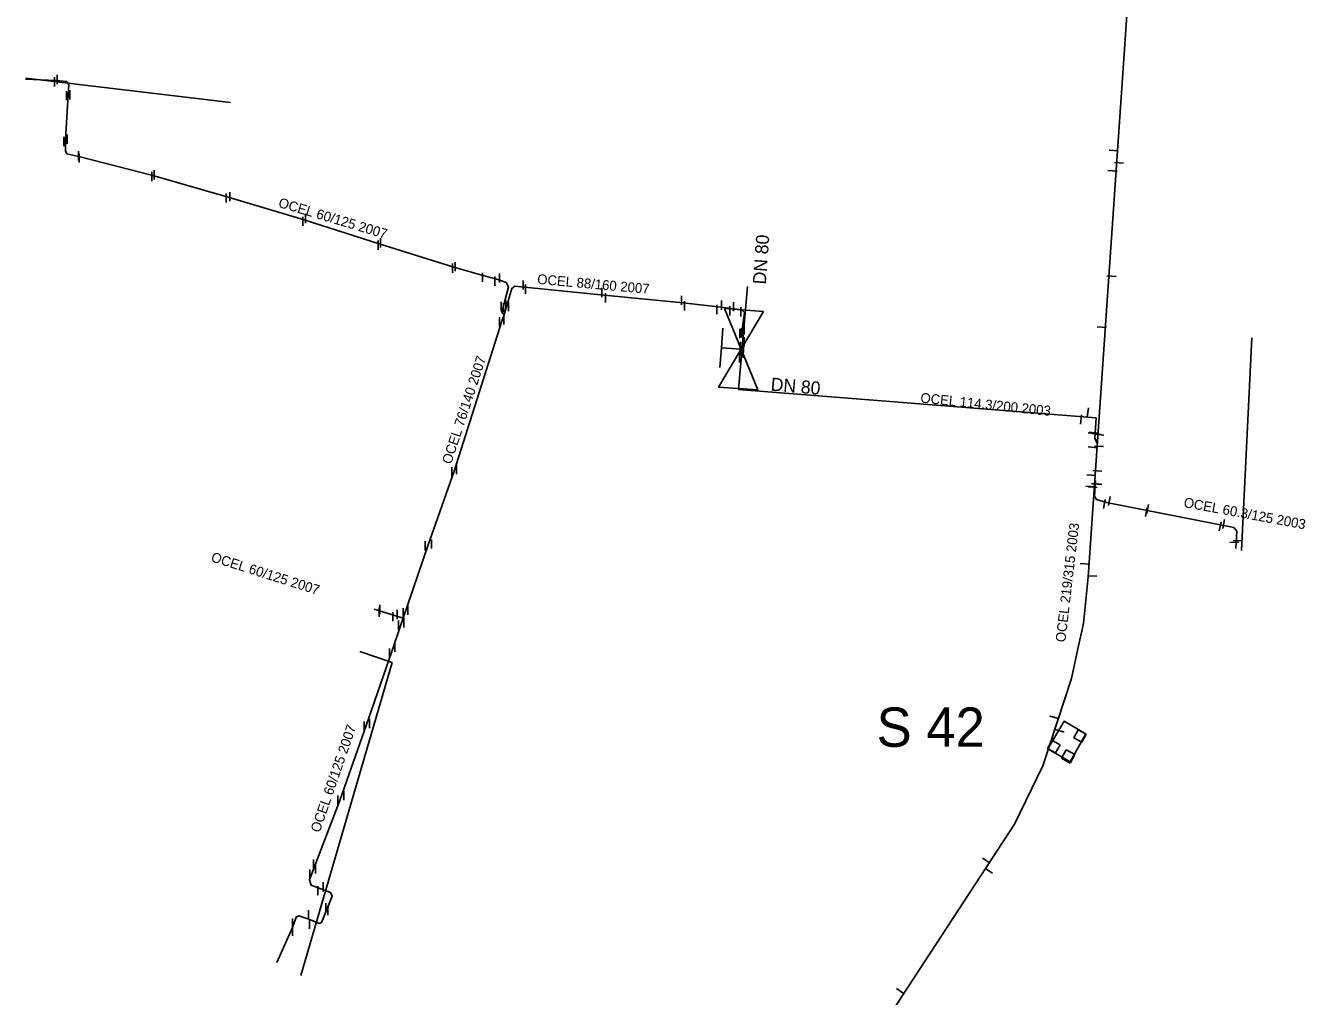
# Model space of a CAD drawing. Extents: x -642943 to -623314, y -1138561 to -1113539.
# Drawn here: x -642449.3 to -642351.7, y -1114344.1 to -1114270 of the extents above; entities that cross this region are included whole.
import ezdxf

# ---------------------------------------------------------------- set-up
doc = ezdxf.new("R2010")
doc.units = 0
for name, color, linetype in [('horkovod armatury', 7, 'Continuous'), ('horkovod dimenze', 7, 'Continuous'), ('horkovod předisol', 7, 'Continuous'), ('horkovod sváry', 7, 'Continuous'), ('horkovod trasa', 7, 'Continuous'), ('horkovod zrušený', 7, 'Continuous'), ('horkovod číslo šachty', 7, 'Continuous')]:
    doc.layers.add(name, color=color, linetype=linetype)

# ---------------------------------------------------------------- blocks, each defined once
blk = doc.blocks.new('POINT_DISPLAY')
blk.add_line((0, 0), (0, 0))
blk = doc.blocks.new('SPH')
at = {"layer": 'horkovod sváry'}
blk.add_line((0, -0.035), (0, 0.035), dxfattribs=at)
blk = doc.blocks.new('SCH_01_88')
at = {"layer": 'horkovod armatury'}
for p, q in [((10, 5), (-10, -5)), ((-10, -5), (-10, 5)), ((-10, 5), (10, -5)), ((-5, 5), (0, 5)), ((0, 5), (0, 0)), ((5, 5), (0, 5)), ((10, -5), (10, 5))]:
    blk.add_line(p, q, dxfattribs=at)

msp = doc.modelspace()

# ---------------------------------------------------------------- linework, layer by layer
at = {"layer": 'horkovod předisol'}
for p, q in [((-642394.555, -1114293.711), (-642394.233, -1114289.932)), ((-642394.555, -1114293.711), (-642394.787, -1114296.346)), ((-642394.787, -1114296.346), (-642394.915, -1114297.796)), ((-642420.473, -1114315.229), (-642422.686, -1114314.538))]:
    msp.add_line(p, q, dxfattribs=at)
for points in [[(-642371.694, -1114326.483), (-642369.526, -1114319.82), (-642369.046, -1114317.552), (-642368.598, -1114315.631), (-642368.252, -1114312.08), (-642364.358, -1114255.556)], [(-642412.791, -1114292.068), (-642412.963, -1114291.918), (-642412.446, -1114289.948), (-642412.619, -1114289.625), (-642413.276, -1114289.409), (-642414.483, -1114289.054), (-642416.625, -1114288.464), (-642422.312, -1114286.679), (-642428.029, -1114284.852), (-642433.828, -1114283.129), (-642439.575, -1114281.465), (-642445.223, -1114280.023), (-642446.125, -1114279.811), (-642446.233, -1114279.584), (-642446.222, -1114278.723), (-642446.017, -1114275.326), (-642445.985, -1114274.561), (-642446.136, -1114274.305), (-642446.966, -1114274.228), (-642449.275, -1114274.122)], [(-642394.555, -1114293.711), (-642394.686, -1114293.606), (-642394.449, -1114291.905), (-642394.664, -1114291.722), (-642396.249, -1114291.507), (-642399.123, -1114291.185), (-642405.148, -1114290.593), (-642411.24, -1114289.971), (-642411.962, -1114289.896), (-642412.199, -1114290.079), (-642412.791, -1114292.068)], [(-642412.791, -1114292.068), (-642412.965, -1114292.574), (-642416.605, -1114304.017), (-642418.591, -1114309.716), (-642420.473, -1114315.229)], [(-642394.915, -1114297.796), (-642367.647, -1114299.956), (-642367.748, -1114301.491), (-642367.55, -1114301.897)], [(-642367.745, -1114304.715), (-642367.685, -1114304.753), (-642367.753, -1114305.909), (-642367.619, -1114306.172), (-642366.851, -1114306.397), (-642357.138, -1114308.307), (-642356.919, -1114308.587), (-642356.986, -1114309.899)], [(-642420.473, -1114315.229), (-642420.674, -1114315.801), (-642421.351, -1114317.759), (-642423.303, -1114323.399), (-642425.282, -1114329.053), (-642427.262, -1114334.222), (-642427.633, -1114335.176), (-642427.498, -1114335.582), (-642426.771, -1114335.86), (-642426.015, -1114336.138), (-642425.901, -1114336.415), (-642426.315, -1114337.438), (-642426.707, -1114338.42), (-642426.893, -1114338.499), (-642427.684, -1114338.171), (-642428.439, -1114337.908), (-642428.632, -1114338.029), (-642428.924, -1114338.802), (-642430.104, -1114341.482)], [(-642402.449, -1114374.66), (-642373.861, -1114330.923), (-642371.694, -1114326.483)]]:
    msp.add_lwpolyline(points, dxfattribs=at)
at = {"layer": 'horkovod trasa'}
for p, q in [((-642394.555, -1114293.711), (-642394.233, -1114289.932)), ((-642394.555, -1114293.711), (-642394.787, -1114296.346)), ((-642394.787, -1114296.346), (-642394.915, -1114297.796)), ((-642420.473, -1114315.229), (-642422.686, -1114314.538))]:
    msp.add_line(p, q, dxfattribs=at)
for points in [[(-642371.694, -1114326.483), (-642369.526, -1114319.82), (-642369.046, -1114317.552), (-642368.598, -1114315.631), (-642368.252, -1114312.08), (-642364.358, -1114255.556)], [(-642412.791, -1114292.068), (-642412.963, -1114291.918), (-642412.446, -1114289.948), (-642412.619, -1114289.625), (-642413.276, -1114289.409), (-642414.483, -1114289.054), (-642416.625, -1114288.464), (-642422.312, -1114286.679), (-642428.029, -1114284.852), (-642433.828, -1114283.129), (-642439.575, -1114281.465), (-642445.223, -1114280.023), (-642446.125, -1114279.811), (-642446.233, -1114279.584), (-642446.222, -1114278.723), (-642446.017, -1114275.326), (-642445.985, -1114274.561), (-642446.136, -1114274.305), (-642446.966, -1114274.228), (-642449.275, -1114274.122)], [(-642394.555, -1114293.711), (-642394.686, -1114293.606), (-642394.449, -1114291.905), (-642394.664, -1114291.722), (-642396.249, -1114291.507), (-642399.123, -1114291.185), (-642405.148, -1114290.593), (-642411.24, -1114289.971), (-642411.962, -1114289.896), (-642412.199, -1114290.079), (-642412.791, -1114292.068)], [(-642412.791, -1114292.068), (-642412.965, -1114292.574), (-642416.605, -1114304.017), (-642418.591, -1114309.716), (-642420.473, -1114315.229)], [(-642394.915, -1114297.796), (-642367.647, -1114299.956), (-642367.748, -1114301.491), (-642367.55, -1114301.897)], [(-642367.745, -1114304.715), (-642367.685, -1114304.753), (-642367.753, -1114305.909), (-642367.619, -1114306.172), (-642366.851, -1114306.397), (-642357.138, -1114308.307), (-642356.919, -1114308.587), (-642356.986, -1114309.899)], [(-642420.473, -1114315.229), (-642420.674, -1114315.801), (-642421.351, -1114317.759), (-642423.303, -1114323.399), (-642425.282, -1114329.053), (-642427.262, -1114334.222), (-642427.633, -1114335.176), (-642427.498, -1114335.582), (-642426.771, -1114335.86), (-642426.015, -1114336.138), (-642425.901, -1114336.415), (-642426.315, -1114337.438), (-642426.707, -1114338.42), (-642426.893, -1114338.499), (-642427.684, -1114338.171), (-642428.439, -1114337.908), (-642428.632, -1114338.029), (-642428.924, -1114338.802), (-642430.104, -1114341.482)], [(-642402.449, -1114374.66), (-642373.861, -1114330.923), (-642371.694, -1114326.483)]]:
    msp.add_lwpolyline(points, dxfattribs=at)
at = {"layer": 'horkovod zrušený'}
for p, q in [((-642433.661, -1114275.908), (-642449.265, -1114274.057)), ((-642355.768, -1114293.853), (-642356.548, -1114310.057)), ((-642421.313, -1114318.591), (-642423.776, -1114317.758)), ((-642428.276, -1114342.47), (-642421.313, -1114318.591)), ((-642369.017, -1114323.727), (-642369.347, -1114324.343)), ((-642368.401, -1114324.057), (-642369.017, -1114323.727)), ((-642370.993, -1114324.542), (-642371.342, -1114325.149)), ((-642370.386, -1114324.891), (-642370.993, -1114324.542)), ((-642369.347, -1114324.343), (-642368.731, -1114324.673)), ((-642368.731, -1114324.673), (-642368.401, -1114324.057)), ((-642371.342, -1114325.149), (-642370.735, -1114325.498)), ((-642370.735, -1114325.498), (-642370.386, -1114324.891)), ((-642369.914, -1114325.251), (-642370.281, -1114325.906)), ((-642369.26, -1114325.618), (-642369.914, -1114325.251)), ((-642369.627, -1114326.273), (-642369.26, -1114325.618)), ((-642370.281, -1114325.906), (-642369.627, -1114326.273))]:
    msp.add_line(p, q, dxfattribs=at)
msp.add_lwpolyline([(-642368.406, -1114324.057), (-642370.086, -1114323.075), (-642371.314, -1114325.172), (-642369.614, -1114326.168), (-642368.424, -1114324.049)], dxfattribs=at)

# ---------------------------------------------------------------- block references
at = {"layer": 'horkovod armatury', "xscale": 0.3000019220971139, "yscale": 0.30000192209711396, "rotation": 85.73202802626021}
msp.add_blockref('SCH_01_88', (-642394.718, -1114294.717), dxfattribs=at)
at = {"layer": 'horkovod sváry', "xscale": 10, "yscale": 10}
for p in [(-642446.861, -1114274.14), (-642447.071, -1114274.32), (-642446.151, -1114275.38), (-642445.911, -1114275.31), (-642446.371, -1114278.87), (-642446.111, -1114278.69), (-642445.241, -1114279.95), (-642445.181, -1114280.13), (-642439.661, -1114281.54), (-642439.481, -1114281.41), (-642433.691, -1114283.08), (-642433.991, -1114283.18), (-642428.131, -1114284.96), (-642427.931, -1114284.75), (-642422.401, -1114286.78), (-642422.201, -1114286.6), (-642416.731, -1114288.53), (-642416.521, -1114288.42), (-642414.421, -1114289.23), (-642413.481, -1114289.52), (-642413.131, -1114289.28), (-642411.341, -1114289.82), (-642411.141, -1114290.14), (-642405.341, -1114290.39), (-642405.051, -1114290.8), (-642413.011, -1114291.46), (-642412.831, -1114291.54), (-642412.66, -1114291.337), (-642412.461, -1114291.45), (-642399.251, -1114290.98), (-642399.021, -1114291.41), (-642396.561, -1114291.68), (-642396.211, -1114291.36), (-642395.561, -1114291.78), (-642395.301, -1114291.47), (-642394.721, -1114291.86), (-642413.131, -1114292.63), (-642412.801, -1114292.47), (-642394.811, -1114293.51), (-642394.671, -1114293.46), (-642394.521, -1114293.23), (-642394.481, -1114293.23), (-642394.761, -1114294.49), (-642394.521, -1114294.58), (-642394.481, -1114294.15), (-642394.841, -1114295.38), (-642394.788, -1114294.851), (-642394.551, -1114295.03), (-642416.771, -1114304.06), (-642416.411, -1114303.88), (-642418.811, -1114309.71), (-642418.331, -1114309.57), (-642422.311, -1114314.77), (-642422.271, -1114314.56), (-642421.281, -1114315.11), (-642420.934, -1114314.943), (-642420.481, -1114314.81), (-642420.131, -1114314.62), (-642420.831, -1114315.75), (-642420.441, -1114315.57), (-642421.531, -1114317.89), (-642421.111, -1114317.43), (-642423.461, -1114323.45), (-642423.059, -1114323.258), (-642425.011, -1114328.74), (-642425.461, -1114329.1), (-642427.591, -1114334.74), (-642427.331, -1114333.97), (-642427.161, -1114334.35), (-642426.571, -1114335.71), (-642427.001, -1114336), (-642426.391, -1114337.3), (-642426.221, -1114337.51), (-642428.931, -1114338.47), (-642427.691, -1114337.83), (-642427.631, -1114338.55), (-642428.921, -1114339.1)]:
    msp.add_blockref('SPH', p, dxfattribs=at)
at = {"layer": 'horkovod sváry'}
for p, xscale, yscale, rotation in [((-642366.299, -1114279.56), 10.000021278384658, 10.000021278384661, 85.68944904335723), ((-642365.899, -1114280.51), 9.999998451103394, 9.999998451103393, 86.12490894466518), ((-642366.389, -1114281.11), 9.999990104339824, 9.999990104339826, 86.16929566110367), ((-642366.469, -1114289.15), 10.000022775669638, 10.000022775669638, 86.40539184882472), ((-642367.199, -1114293.03), 9.99998019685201, 9.999980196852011, 86.39227720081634), ((-642368.259, -1114299.54), 9.999986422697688, 9.99998642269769, -8.333930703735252), ((-642368.789, -1114300.07), 9.999982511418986, 9.999982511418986, -5.452385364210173), ((-642367.889, -1114301.12), 10.000023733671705, 10.000023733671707, 83.43883083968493), ((-642367.829, -1114301.07), 9.999989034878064, 9.999989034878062, 82.99547567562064), ((-642367.599, -1114301.18), 9.999993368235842, 9.999993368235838, 83.48016795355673), ((-642367.399, -1114301.23), 10.000022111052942, 10.000022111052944, 83.18013545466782), ((-642367.889, -1114302.2), 10.000015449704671, 10.000015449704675, 84.55406502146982), ((-642367.419, -1114302.12), 10.000010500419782, 10.000010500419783, 86.14764366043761), ((-642367.549, -1114303.98), 10.000014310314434, 10.000014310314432, 85.93101611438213), ((-642368.069, -1114305.19), 10.000009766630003, 10.00000976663, 85.45529121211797), ((-642368.009, -1114304.32), 10.00000136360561, 10.000001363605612, 86.36501632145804), ((-642367.639, -1114304.98), 9.999990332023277, 9.999990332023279, 85.66348173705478), ((-642367.559, -1114305.01), 9.999976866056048, 9.999976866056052, 85.81169604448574), ((-642367.909, -1114305.23), 10.000015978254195, 10.000015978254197, 85.68275769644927), ((-642366.629, -1114306.28), 10.000009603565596, 10.000009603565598, -11.602690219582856), ((-642367.019, -1114306.51), 10.00002216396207, 10.00002216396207, -10.957890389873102), ((-642363.819, -1114307.13), 9.999975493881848, 9.99997549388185, -10.753920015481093), ((-642363.709, -1114306.89), 9.999989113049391, 9.999989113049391, -11.07698196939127), ((-642358.179, -1114308.22), 9.999989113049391, 9.999989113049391, -11.07698196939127), ((-642357.909, -1114308.03), 9.999989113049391, 9.999989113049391, -11.07698196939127), ((-642357.103, -1114309.438), 9.999965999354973, 9.999965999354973, -92.59530530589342), ((-642356.829, -1114309.311), 9.999991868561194, 9.999991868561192, -92.62200675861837), ((-642368.519, -1114311.08), 10.000013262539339, 10.000013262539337, 86.50990864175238), ((-642367.929, -1114312.01), 10.000024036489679, 10.00002403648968, 87.27116358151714), ((-642370.829, -1114322.79), 9.9999798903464, 9.999979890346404, 74.60789540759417), ((-642370.419, -1114323.81), 9.99998961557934, 9.999989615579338, 72.54388847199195), ((-642376.019, -1114333.71), 9.999989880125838, 9.99998988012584, 58.17035689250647), ((-642375.839, -1114334.47), 9.999988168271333, 9.999988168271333, 56.74193923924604), ((-642382.559, -1114343.66), 9.9999893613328, 9.999989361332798, 56.443425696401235)]:
    msp.add_blockref('SPH', p, dxfattribs=dict(at, xscale=xscale, yscale=yscale, rotation=rotation))
at = {"layer": 'horkovod zrušený'}
for p in [(-642368.874, -1114324.2), (-642370.864, -1114325.02), (-642369.764, -1114325.76)]:
    msp.add_blockref('POINT_DISPLAY', p, dxfattribs=at)

# ---------------------------------------------------------------- texts
at = {"layer": 'horkovod dimenze'}
for s, height, rotation, p in [('OCEL 60/125 2007', 0.74996, 343.41064, (-642430.051, -1114283.857)), ('DN 80', 1, 85.86478, (-642392.828, -1114289.795)), ('OCEL 88/160 2007', 0.75, 354.90047, (-642410.282, -1114289.728)), ('OCEL 76/140 2007', 0.74996, 71.79843, (-642416.829, -1114303.535)), ('DN 80', 1, 355.06306, (-642392.484, -1114297.866)), ('OCEL 114.3/200 2003', 0.75, 354.12426, (-642381.065, -1114298.776)), ('OCEL 60.3/125 2003', 0.74998, 349.51482, (-642361.003, -1114306.738)), ('OCEL 219/315 2003', 0.74996, 83.26948, (-642369.993, -1114317.085)), ('OCEL 60/125 2007', 0.75, 342.48461, (-642435.191, -1114310.875)), ('OCEL 60/125 2007', 0.75, 70.88958, (-642426.859, -1114331.621))]:
    msp.add_text(s, height=height, rotation=rotation, dxfattribs=at).set_placement(p)
at = {"layer": 'horkovod číslo šachty'}
msp.add_text('S 42', height=3, dxfattribs=at).set_placement((-642384.38, -1114325.031))

doc.saveas('drawing.dxf')
